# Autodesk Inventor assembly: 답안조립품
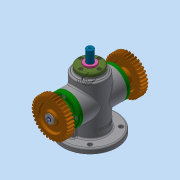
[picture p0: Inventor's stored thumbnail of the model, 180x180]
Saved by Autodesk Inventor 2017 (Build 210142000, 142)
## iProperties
Part Number: 답안조립품
Material: 일반
Document SubType Name: Assembly
Designer: mrc
Author: mrc
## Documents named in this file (17)
- C:\Users\mrc\Desktop\600606V1014\답안조립품.iam
- C:\Users\mrc\Desktop\600606V1014\본체.ipt
- C:\Users\mrc\Desktop\600606V1014\가변스프링.ipt
- C:\Users\mrc\Desktop\600606V1014\멈춤링.ipt
- C:\Users\mrc\Desktop\600606V1014\베어링 6203.ipt
- C:\Users\mrc\Desktop\600606V1014\볼트 M4.ipt
- C:\Users\mrc\Desktop\600606V1014\부시.ipt
- C:\Users\mrc\Desktop\600606V1014\스퍼기어.ipt
- C:\Users\mrc\Desktop\600606V1014\스프링와셔.ipt
- C:\Users\mrc\Desktop\600606V1014\스프링조립용 와셔.ipt
- C:\Users\mrc\Desktop\600606V1014\슬라이더.ipt
- C:\Users\mrc\Desktop\600606V1014\오일 실 17 30 8.ipt
- C:\Users\mrc\Desktop\600606V1014\커버 A.ipt
- C:\Users\mrc\Desktop\600606V1014\커버 B.ipt
- C:\Users\mrc\Desktop\600606V1014\키 4x4x12.ipt
- C:\Users\mrc\Desktop\600606V1014\편심축.ipt
- C:\Users\mrc\Desktop\600606V1014\평와셔.ipt
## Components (1 placed, 1 different names)
1. 가변스프링:1
